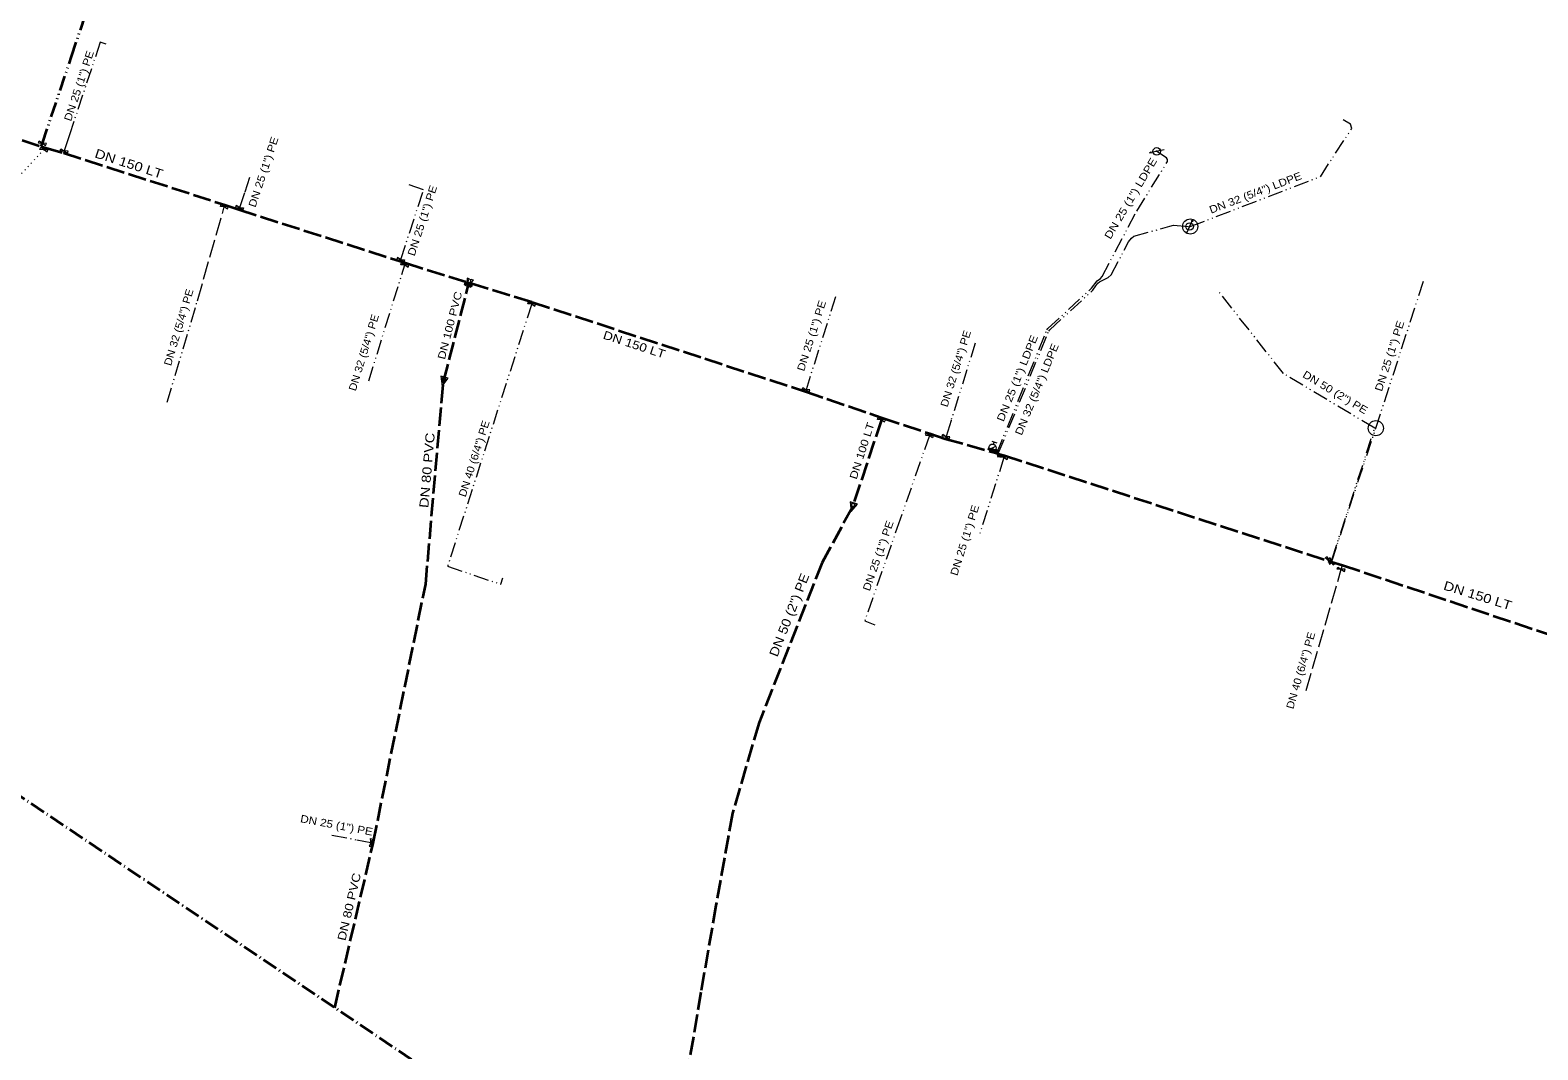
# Model space of a CAD drawing. Extents: x -635202 to -632824, y -1037605 to -1036177.
# Drawn here: x -634347.6 to -634148.5, y -1037321.7 to -1037187.1 of the extents above; entities that cross this region are included whole.
import ezdxf
from ezdxf.enums import TextEntityAlignment as Align

# ---------------------------------------------------------------- set-up
doc = ezdxf.new("R2010")
doc.units = 0
doc.header["$LTSCALE"] = 0.4
for name, pattern in [('DASH_DOUBLE_DOT', [9.2, 5, -1.2, 0.3, -1.2, 0.3, -1.2]), ('DOT_DASHED', [7.7, 5, -1.2, 0.3, -1.2]), ('DOTTED', [1.5, 0.3, -1.2]), ('LONG_DASHED', [7.5, 6, -1.5])]:
    doc.linetypes.add(name, pattern=pattern)
for name, color, linetype, lineweight in [('10', 7, 'Continuous', 13), ('12', 7, 'Continuous', 13), ('21', 7, 'LONG_DASHED', 35), ('22', 7, 'DASH_DOUBLE_DOT', 35), ('31', 7, 'LONG_DASHED', 13), ('32', 7, 'DASH_DOUBLE_DOT', 13), ('63', 7, 'DOT_DASHED', 40)]:
    doc.layers.add(name, color=color, linetype=linetype, lineweight=lineweight)
doc.layers.add('29', color=7, linetype='Continuous')
doc.layers.add('39', color=7, linetype='Continuous')

msp = doc.modelspace()

# ---------------------------------------------------------------- linework, layer by layer
at = {"layer": '10'}
for p, q in [((-634220.647, -1037241.366), (-634219.978, -1037241.57)), ((-634220.4, -1037241.755), (-634220.312, -1037241.468)), ((-634220.988, -1037242.468), (-634220.105, -1037241.999))]:
    msp.add_line(p, q, dxfattribs=at)
for points in [[(-634345.465, -1037202.029), (-634346.509, -1037201.995), (-634346.413, -1037201.711), (-634345.561, -1037202.313)], [(-634345.267, -1037202.86), (-634346.31, -1037202.816), (-634346.212, -1037202.533), (-634345.365, -1037203.143)], [(-634342.588, -1037203.052), (-634343.631, -1037203.013), (-634343.534, -1037202.729), (-634342.685, -1037203.335)], [(-634321.448, -1037210.41), (-634322.491, -1037210.367), (-634322.393, -1037210.084), (-634321.546, -1037210.694)], [(-634320.48, -1037210.507), (-634319.436, -1037210.539), (-634319.531, -1037210.824), (-634320.385, -1037210.222)], [(-634299.205, -1037217.366), (-634298.161, -1037217.388), (-634298.254, -1037217.673), (-634299.113, -1037217.08)], [(-634297.616, -1037218.071), (-634298.659, -1037218.049), (-634298.567, -1037217.764), (-634297.708, -1037218.357)], [(-634289.887, -1037219.834), (-634289.896, -1037220.878), (-634290.183, -1037220.789), (-634289.6, -1037219.923)], [(-634289.423, -1037221.023), (-634289.416, -1037219.979), (-634289.129, -1037220.067), (-634289.71, -1037220.935)], [(-634289.198, -1037220.652), (-634290.241, -1037220.691), (-634290.166, -1037220.401), (-634289.273, -1037220.942)], [(-634280.866, -1037223.23), (-634281.91, -1037223.227), (-634281.823, -1037222.94), (-634280.953, -1037223.517)], [(-634292.403, -1037233.043), (-634293.371, -1037232.792), (-634293.189, -1037234.079)], [(-634292.659, -1037233.131), (-634293.191, -1037232.993), (-634293.091, -1037233.701)], [(-634244.644, -1037234.568), (-634245.688, -1037234.552), (-634245.597, -1037234.266), (-634244.734, -1037234.854)], [(-634234.694, -1037238.53), (-634235.737, -1037238.509), (-634235.645, -1037238.223), (-634234.786, -1037238.815)], [(-634229.403, -1037240.57), (-634228.359, -1037240.616), (-634228.458, -1037240.899), (-634229.304, -1037240.287)], [(-634226.158, -1037240.774), (-634227.2, -1037240.713), (-634227.097, -1037240.431), (-634226.261, -1037241.056)], [(-634220.063, -1037242.501), (-634221.107, -1037242.488), (-634221.017, -1037242.202), (-634220.153, -1037242.787)], [(-634219.596, -1037243.296), (-634220.347, -1037242.571), (-634220.085, -1037242.425), (-634219.857, -1037243.443)], [(-634220.185, -1037242.662), (-634219.374, -1037243.32), (-634219.623, -1037243.489), (-634219.937, -1037242.493)], [(-634218.519, -1037243.504), (-634219.563, -1037243.489), (-634219.473, -1037243.203), (-634218.61, -1037243.79)], [(-634238.377, -1037249.667), (-634239.326, -1037249.353), (-634239.228, -1037250.65)], [(-634238.638, -1037249.739), (-634239.16, -1037249.566), (-634239.106, -1037250.279)], [(-634175.806, -1037257.427), (-634176.625, -1037256.78), (-634176.38, -1037256.608), (-634176.052, -1037257.599)], [(-634176.185, -1037256.937), (-634175.339, -1037257.548), (-634175.576, -1037257.73), (-634175.947, -1037256.754)], [(-634173.976, -1037258.268), (-634175.02, -1037258.265), (-634174.933, -1037257.978), (-634174.063, -1037258.555)], [(-634302.557, -1037294.884), (-634302.667, -1037293.845), (-634302.372, -1037293.901), (-634302.852, -1037294.828)]]:
    msp.add_lwpolyline(points, close=True, dxfattribs=at)
for centre, radius in [((-634194.438, -1037213.003), 1), ((-634169.931, -1037239.643), 1), ((-634220.546, -1037242.233), 0.5)]:
    msp.add_circle(centre, radius, dxfattribs=at)
at = {"layer": '12'}
for p, q in [((-634197.878, -1037202.89), (-634199.838, -1037203.29)), ((-634194.924, -1037213.918), (-634194.108, -1037212.092))]:
    msp.add_line(p, q, dxfattribs=at)
for points in [[(-634199.541, -1037203.336), (-634199.838, -1037203.29), (-634199.582, -1037203.133)], [(-634194.318, -1037212.307), (-634194.108, -1037212.092), (-634194.129, -1037212.391)]]:
    msp.add_lwpolyline(points, dxfattribs=at)
for centre in [(-634198.8586, -1037203.091), (-634194.5163, -1037213.0043)]:
    msp.add_circle(centre, 0.5, dxfattribs=at)
at = {"layer": '21'}
for p, q in [((-634365.753, -1037195.927), (-634346.133, -1037202.449)), ((-634346.133, -1037202.449), (-634345.708, -1037202.588)), ((-634345.708, -1037202.588), (-634343.189, -1037203.274)), ((-634343.189, -1037203.274), (-634321.901, -1037210.149)), ((-634321.901, -1037210.149), (-634320.037, -1037210.76)), ((-634320.037, -1037210.76), (-634298.756, -1037217.602)), ((-634298.756, -1037217.602), (-634298.068, -1037217.823)), ((-634298.068, -1037217.823), (-634289.892, -1037220.356)), ((-634293.038, -1037233.498), (-634289.719, -1037220.671)), ((-634289.892, -1037220.356), (-634289.652, -1037220.43)), ((-634281.315, -1037222.989), (-634245.238, -1037234.803)), ((-634245.238, -1037234.803), (-634235.132, -1037238.262)), ((-634235.216, -1037238.519), (-634239.04, -1037250.08)), ((-634235.132, -1037238.262), (-634235.216, -1037238.519)), ((-634228.799, -1037240.357), (-634226.776, -1037241.026)), ((-634226.776, -1037241.026), (-634220.655, -1037242.767)), ((-634220.655, -1037242.767), (-634220.585, -1037242.495)), ((-634220.655, -1037242.767), (-634219.981, -1037242.958)), ((-634220.585, -1037242.495), (-634220.546, -1037242.233)), ((-634219.981, -1037242.958), (-634219.789, -1037243.013)), ((-634219.789, -1037243.013), (-634218.962, -1037243.248)), ((-634218.962, -1037243.248), (-634176.234, -1037257.156)), ((-634175.779, -1037257.296), (-634174.338, -1037257.738)), ((-634307.39, -1037316.173), (-634302.32, -1037294.429))]:
    msp.add_line(p, q, dxfattribs=at)
for points in [[(-634289.72, -1037220.672), (-634289.652, -1037220.43), (-634289.419, -1037220.501), (-634281.315, -1037222.989)], [(-634302.32, -1037294.429), (-634295.381, -1037260.231), (-634293.038, -1037233.498), (-634293.038, -1037233.498)], [(-634235.132, -1037238.262), (-634228.799, -1037240.357), (-634228.799, -1037240.357)], [(-634239.04, -1037250.08), (-634243.05, -1037257.36), (-634251.37, -1037278.53), (-634254.88, -1037290.49), (-634257.06, -1037302.66), (-634259.05, -1037314.11), (-634261.22, -1037327.01), (-634262.059, -1037338.267)], [(-634176.234, -1037257.156), (-634175.779, -1037257.296), (-634175.779, -1037257.296)], [(-634174.338, -1037257.738), (-634141.388, -1037268.767), (-634141.388, -1037268.767)]]:
    msp.add_lwpolyline(points, dxfattribs=at)
at = {"layer": '22'}
msp.add_line((-634346.133, -1037202.449), (-634345.987, -1037202.012), dxfattribs=at)
msp.add_lwpolyline([(-634345.987, -1037202.012), (-634342.145, -1037190.56), (-634320.05, -1037124.697)], dxfattribs=at)
at = {"layer": '31'}
for p, q in [((-634342.426, -1037200.921), (-634343.109, -1037203.032)), ((-634345.708, -1037202.588), (-634345.788, -1037202.838)), ((-634343.109, -1037203.032), (-634343.189, -1037203.274)), ((-634319.295, -1037208.538), (-634319.958, -1037210.523)), ((-634319.958, -1037210.523), (-634320.037, -1037210.76)), ((-634298.138, -1037218.06), (-634298.068, -1037217.823)), ((-634281.315, -1037222.989), (-634281.388, -1037223.228)), ((-634244.613, -1037232.814), (-634245.166, -1037234.56)), ((-634245.166, -1037234.56), (-634245.238, -1037234.803)), ((-634226.024, -1037238.623), (-634226.679, -1037240.743)), ((-634226.679, -1037240.743), (-634226.776, -1037241.026)), ((-634174.498, -1037258.267), (-634174.338, -1037257.738)), ((-634179.15, -1037274.277), (-634174.498, -1037258.267)), ((-634304.464, -1037294.015), (-634302.612, -1037294.364)), ((-634302.612, -1037294.364), (-634302.32, -1037294.429))]:
    msp.add_line(p, q, dxfattribs=at)
msp.add_lwpolyline([(-634325.529, -1037222.824), (-634321.97, -1037210.389), (-634321.901, -1037210.149)], dxfattribs=at)
at = {"layer": '32'}
for p, q in [((-634198.859, -1037203.091), (-634198.982, -1037203.01)), ((-634318.632, -1037206.553), (-634319.295, -1037208.538)), ((-634302.898, -1037233.384), (-634298.138, -1037218.06)), ((-634298.756, -1037217.602), (-634298.683, -1037217.377)), ((-634169.931, -1037239.643), (-634163.55, -1037219.941)), ((-634329.51, -1037236.208), (-634325.529, -1037222.824)), ((-634241.279, -1037222.303), (-634244.613, -1037232.814)), ((-634219.981, -1037242.958), (-634219.971, -1037242.934)), ((-634219.789, -1037243.013), (-634219.78, -1037242.991)), ((-634176.234, -1037257.156), (-634176.216, -1037257.103)), ((-634175.779, -1037257.296), (-634175.762, -1037257.242)), ((-634307.779, -1037293.391), (-634304.464, -1037294.015))]:
    msp.add_line(p, q, dxfattribs=at)
for points in [[(-634337.586, -1037188.911), (-634338.358, -1037188.68), (-634342.426, -1037200.921)], [(-634194.438, -1037213.003), (-634177.257, -1037206.426), (-634173.118, -1037200.068), (-634173.28, -1037199.49), (-634174.246, -1037198.911)], [(-634219.971, -1037242.934), (-634213.352, -1037226.633), (-634213.224, -1037226.474), (-634207.464, -1037221.159), (-634206.737, -1037220.196), (-634206.29, -1037219.878), (-634206.086, -1037219.597), (-634201.493, -1037210.959), (-634197.444, -1037204.416), (-634197.444, -1037204.166), (-634197.58, -1037203.936), (-634198.859, -1037203.091)], [(-634298.683, -1037217.377), (-634295.669, -1037208.15), (-634297.656, -1037207.487)], [(-634219.78, -1037242.991), (-634213.113, -1037226.826), (-634212.982, -1037226.633), (-634207.485, -1037221.611), (-634207.28, -1037221.394), (-634206.884, -1037220.821), (-634206.622, -1037220.502), (-634206.424, -1037220.305), (-634205.265, -1037219.74), (-634204.877, -1037219.396), (-634202.571, -1037215.052), (-634202.184, -1037214.536), (-634201.903, -1037214.278), (-634197.118, -1037212.976), (-634196.645, -1037212.837), (-634194.516, -1037213.004)], [(-634194.516, -1037213.004), (-634194.438, -1037213.003), (-634194.438, -1037213.003)], [(-634176.216, -1037257.103), (-634175.708, -1037256.912), (-634170.088, -1037239.649), (-634182.11, -1037232.431), (-634190.557, -1037221.755)], [(-634281.388, -1037223.228), (-634292.492, -1037257.867), (-634285.458, -1037260.256), (-634285.193, -1037259.407)], [(-634222.83, -1037228.411), (-634226.017, -1037238.601), (-634226.024, -1037238.623)], [(-634175.762, -1037257.242), (-634169.931, -1037239.643), (-634169.931, -1037239.643)], [(-634228.881, -1037240.593), (-634232.727, -1037251.636), (-634237.407, -1037265.076), (-634236.082, -1037265.606)], [(-634228.799, -1037240.357), (-634228.881, -1037240.593), (-634228.881, -1037240.593)], [(-634218.962, -1037243.248), (-634219.041, -1037243.497), (-634222.292, -1037253.793)]]:
    msp.add_lwpolyline(points, dxfattribs=at)
at = {"layer": '32', "linetype": 'DOTTED'}
msp.add_lwpolyline([(-634345.788, -1037202.838), (-634353.95, -1037211.611), (-634364.673, -1037232.636)], dxfattribs=at)
at = {"layer": '63'}
msp.add_lwpolyline([(-635201.893, -1036293.521), (-635065.737, -1036176.522), (-634666.247, -1036562.377), (-634740.782, -1036634.185), (-633954.528, -1037175.019), (-633883.629, -1037007.77), (-632823.776, -1037286.822), (-632902.856, -1037604.96), (-633921.805, -1037365.902), (-634067.239, -1037477.705), (-635033.469, -1036827.795), (-634902.578, -1036625.096)], close=True, dxfattribs=at)

# ---------------------------------------------------------------- texts
at = {"layer": '29', "width": 1.2}
for s, rotation, p in [('DN 150 LT', 342.234, (-634339.177, -1037203.853)), ('DN 80 PVC', 84.991, (-634295.044, -1037250.212)), ('DN 150 LT', 342.758, (-634161.103, -1037260.927))]:
    msp.add_text(s, height=1.2, rotation=rotation, dxfattribs=at).set_placement(p)
at = {"layer": '29'}
for s, height, rotation, width, p in [('DN 100 PVC', 1, 75.455, 1.2, (-634291.7058, -1037226.1926)), ('DN 150 LT', 1.1, 341.868, 1.2, (-634268.0092, -1037229.1161)), ('DN 100 LT', 1, 72.141, 1.2, (-634237.3102, -1037242.7823)), ('DN 50 (2") PE', 1.2, 68.545, 1.15, (-634246.8291, -1037264.5295)), ('DN 80 PVC', 1.1, 76.874, 1.2, (-634304.9475, -1037302.9629))]:
    msp.add_text(s, height=height, rotation=rotation, dxfattribs=dict(at, width=width)).set_placement(p, align=Align.CENTER)
at = {"layer": '39'}
for s, rotation, width, p in [('DN 25 (1") PE', 71.617, 1.15, (-634340.6895, -1037194.5857)), ('DN 25 (1") PE', 71.53, 1.15, (-634316.3379, -1037205.9654)), ('DN 25 (1") LDPE', 59.319, 1.2, (-634201.8762, -1037209.5521)), ('DN 32 (5/4") LDPE', 20.947, 1.15, (-634185.6488, -1037209.0123)), ('DN 25 (1") PE', 71.91, 1.15, (-634295.3534, -1037212.3833)), ('DN 32 (5/4") PE', 73.435, 1.1, (-634327.5142, -1037226.4525)), ('DN 25 (1") PE', 72.405, 1.15, (-634243.9618, -1037227.5831)), ('DN 32 (5/4") PE', 72.861, 1.1, (-634303.0773, -1037229.7963)), ('DN 25 (1") PE', 72.054, 1.15, (-634167.6466, -1037230.2561)), ('DN 32 (5/4") PE', 72.633, 1.1, (-634224.9265, -1037231.9242)), ('DN 25 (1") LDPE', 67.9, 1.2, (-634216.8071, -1037233.2291)), ('DN 32 (5/4") LDPE', 67.587, 1.15, (-634214.2271, -1037234.6936)), ('DN 50 (2") PE', 329.019, 1.15, (-634175.5484, -1037235.3353)), ('DN 40 (6/4") PE', 72.226, 1.1, (-634288.5187, -1037243.8116)), ('DN 25 (1") PE', 72.463, 1.15, (-634223.7398, -1037254.5857)), ('DN 25 (1") PE', 70.801, 1.15, (-634235.1719, -1037256.6504)), ('DN 40 (6/4") PE', 73.798, 1.1, (-634179.376, -1037271.7685)), ('DN 25 (1") PE', 349.34, 1.15, (-634307.2425, -1037292.5552))]:
    msp.add_text(s, height=1, rotation=rotation, dxfattribs=dict(at, width=width)).set_placement(p, align=Align.CENTER)

doc.saveas('drawing.dxf')
